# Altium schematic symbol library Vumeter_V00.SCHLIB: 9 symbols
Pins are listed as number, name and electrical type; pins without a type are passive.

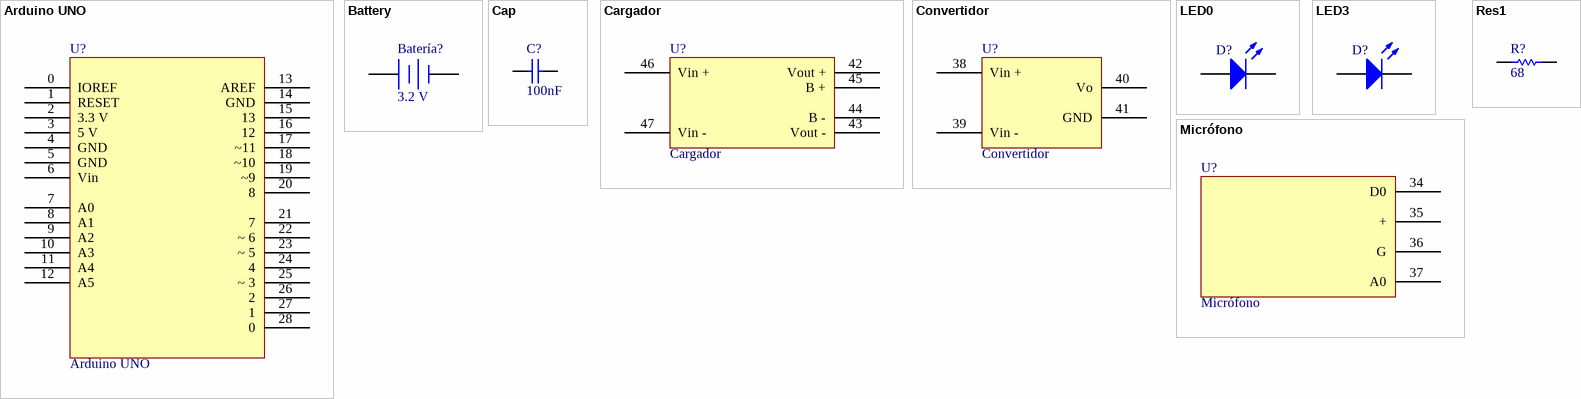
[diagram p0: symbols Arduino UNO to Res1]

## Arduino UNO
designator U?
pins: 0 IOREF, 1 RESET, 2 3.3 V, 3 5 V, 4 GND, 5 GND, 6 Vin, 7 A0, 8 A1, 9 A2, 10 A3, 11 A4, 12 A5, 13 AREF, 14 GND, 15 13, 16 12, 17 ~11, 18 ~10, 19 ~9, 20 8, 21 7, 22 ~ 6, 23 ~ 5, 24 4, 25 ~ 3, 26 2, 27 1, 28 0

## Battery
designator Batería?, comment 3.2 V
Multicell Battery
footprint BAT-2 (Battery; 2 Leads)
pins: 1 +, 2 -

## Cap
designator C?  value 100nF  (hidden comment: Cap)
Capacitor
footprint RAD-0.3 (Radial Cap, Thru-Hole; 2 Leads; 0.3 in Pin Spacing)
simulation model CAP (Capacitor)
signal-integrity model Cap
pins: 1, 2

## Cargador
designator U?
pins: 42 Vout +, 43 Vout -, 44 B -, 45 B +, 46 Vin +, 47 Vin -

## Convertidor
designator U?
pins: 38 Vin +, 39 Vin -, 40 Vo, 41 GND

## LED0
designator D?, comment ED0  (value not drawn)
Typical INFRARED GaAs LED
footprint LED-0 (LED; 2 Leads)
simulation model LED0 (Diode)
pins: 1 A, 2 K

## LED3
designator D?  (value not drawn)
Typical BLUE SiC LED
footprint 3.5X2.8X1.9 (SM LED; 2 C-Bend Leads; Body 3.5 x 2.8 x 1.9 mm, inc leads (LxWxH typ))
simulation model LED3 (Diode)
signal-integrity model LED
pins: 1 A, 2 K

## Micrófono
designator U?
pins: 34 D0, 35 +, 36 G, 37 A0

## Res1
designator R?  value 68  (hidden comment: Res1)
Resistor
footprint AXIAL-0.3 (Axial Device, Thru-Hole; 2 Leads; 0.3 in Pin Spacing)
simulation model RESISTOR (Resistor)
signal-integrity model Res
pins: 1, 2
